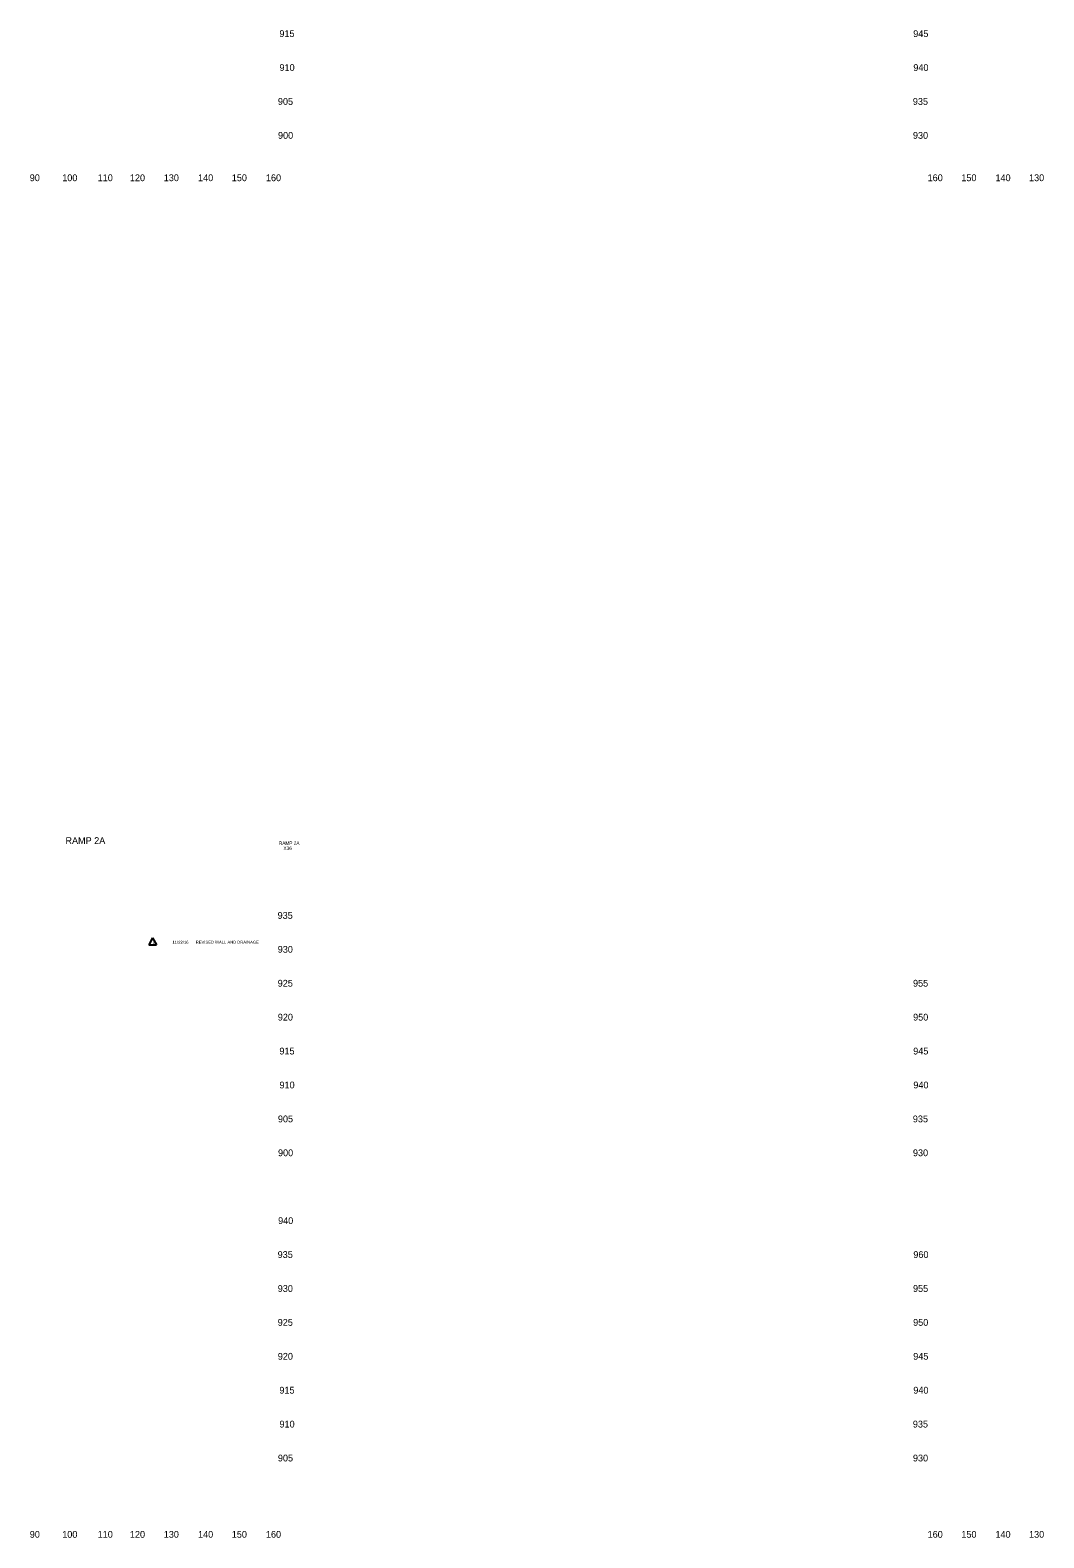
# Model space of a CAD drawing. Extents: x 4994 to 7388, y 4997 to 8804.
# Drawn here: x 6793.6 to 7092.3, y 6997.5 to 7442 of the extents above; entities that cross this region are included whole.
import ezdxf

# ---------------------------------------------------------------- set-up
doc = ezdxf.new("R2010")
doc.units = 0
for name, color, linetype in [('RD_SHT_ID', 7, 'Continuous'), ('RD_SHT_TX', 7, 'Continuous'), ('RD_XS_TX_Offset', 7, 'Continuous')]:
    doc.layers.add(name, color=color, linetype=linetype)

msp = doc.modelspace()

# ---------------------------------------------------------------- linework, layer by layer
at = {"layer": 'RD_SHT_TX'}
for p, q in [((6829.71, 7174.39), (6828.57, 7172.36)), ((6828.57, 7172.36), (6830.85, 7172.36)), ((6829.71, 7174.39), (6830.85, 7172.36))]:
    msp.add_line(p, q, dxfattribs=at)

# ---------------------------------------------------------------- texts
at = {"layer": 'RD_SHT_ID'}
for s, height, p in [('RAMP 2A', 2, (6804.02, 7202.06)), ('RAMP 2A', 1, (6866.93, 7201.8)), ('X36', 1, (6868.26, 7200.3))]:
    msp.add_text(s, height=height, dxfattribs=at).set_placement(p)
at = {"layer": 'RD_SHT_TX'}
for s, p in [('1', (6829.71, 7172.69)), ('11/22/16', (6835.55, 7172.65)), ('REVISED WALL AND DRAINAGE', (6842.44, 7172.65))]:
    msp.add_text(s, height=0.88, dxfattribs=at).set_placement(p)
at = {"layer": 'RD_XS_TX_Offset'}
for s, p in [('915', (6867.07, 7440)), ('945', (7053.86, 7440)), ('910', (6867.1, 7430)), ('940', (7053.89, 7430)), ('905', (6866.63, 7420)), ('935', (7053.75, 7420)), ('900', (6866.66, 7410)), ('930', (7053.78, 7410)), ('90', (6793.5, 7397.5)), ('100', (6803.07, 7397.5)), ('110', (6813.51, 7397.5)), ('120', (6823.01, 7397.5)), ('130', (6832.99, 7397.5)), ('140', (6843.1, 7397.5)), ('150', (6853.04, 7397.5)), ('160', (6863.1, 7397.5)), ('160', (7058.1, 7397.5)), ('150', (7068.04, 7397.5)), ('140', (7078.1, 7397.5)), ('130', (7087.99, 7397.5)), ('935', (6866.55, 7180)), ('930', (6866.58, 7170)), ('925', (6866.57, 7160)), ('955', (7053.8, 7160)), ('920', (6866.6, 7150)), ('950', (7053.83, 7150)), ('915', (6867.07, 7140)), ('945', (7053.86, 7140)), ('910', (6867.1, 7130)), ('940', (7053.89, 7130)), ('905', (6866.63, 7120)), ('935', (7053.75, 7120)), ('900', (6866.66, 7110)), ('930', (7053.78, 7110)), ('940', (6866.69, 7090)), ('935', (6866.55, 7080)), ('960', (7053.89, 7080)), ('930', (6866.58, 7070)), ('955', (7053.8, 7070)), ('925', (6866.57, 7060)), ('950', (7053.83, 7060)), ('920', (6866.6, 7050)), ('945', (7053.86, 7050)), ('915', (6867.07, 7040)), ('940', (7053.89, 7040)), ('910', (6867.1, 7030)), ('935', (7053.75, 7030)), ('905', (6866.63, 7020)), ('930', (7053.78, 7020)), ('90', (6793.5, 6997.5)), ('100', (6803.07, 6997.5)), ('110', (6813.51, 6997.5)), ('120', (6823.01, 6997.5)), ('130', (6832.99, 6997.5)), ('140', (6843.1, 6997.5)), ('150', (6853.04, 6997.5)), ('160', (6863.1, 6997.5)), ('160', (7058.1, 6997.5)), ('150', (7068.04, 6997.5)), ('140', (7078.1, 6997.5)), ('130', (7087.99, 6997.5))]:
    msp.add_text(s, height=2, dxfattribs=at).set_placement(p)

doc.saveas('drawing.dxf')
